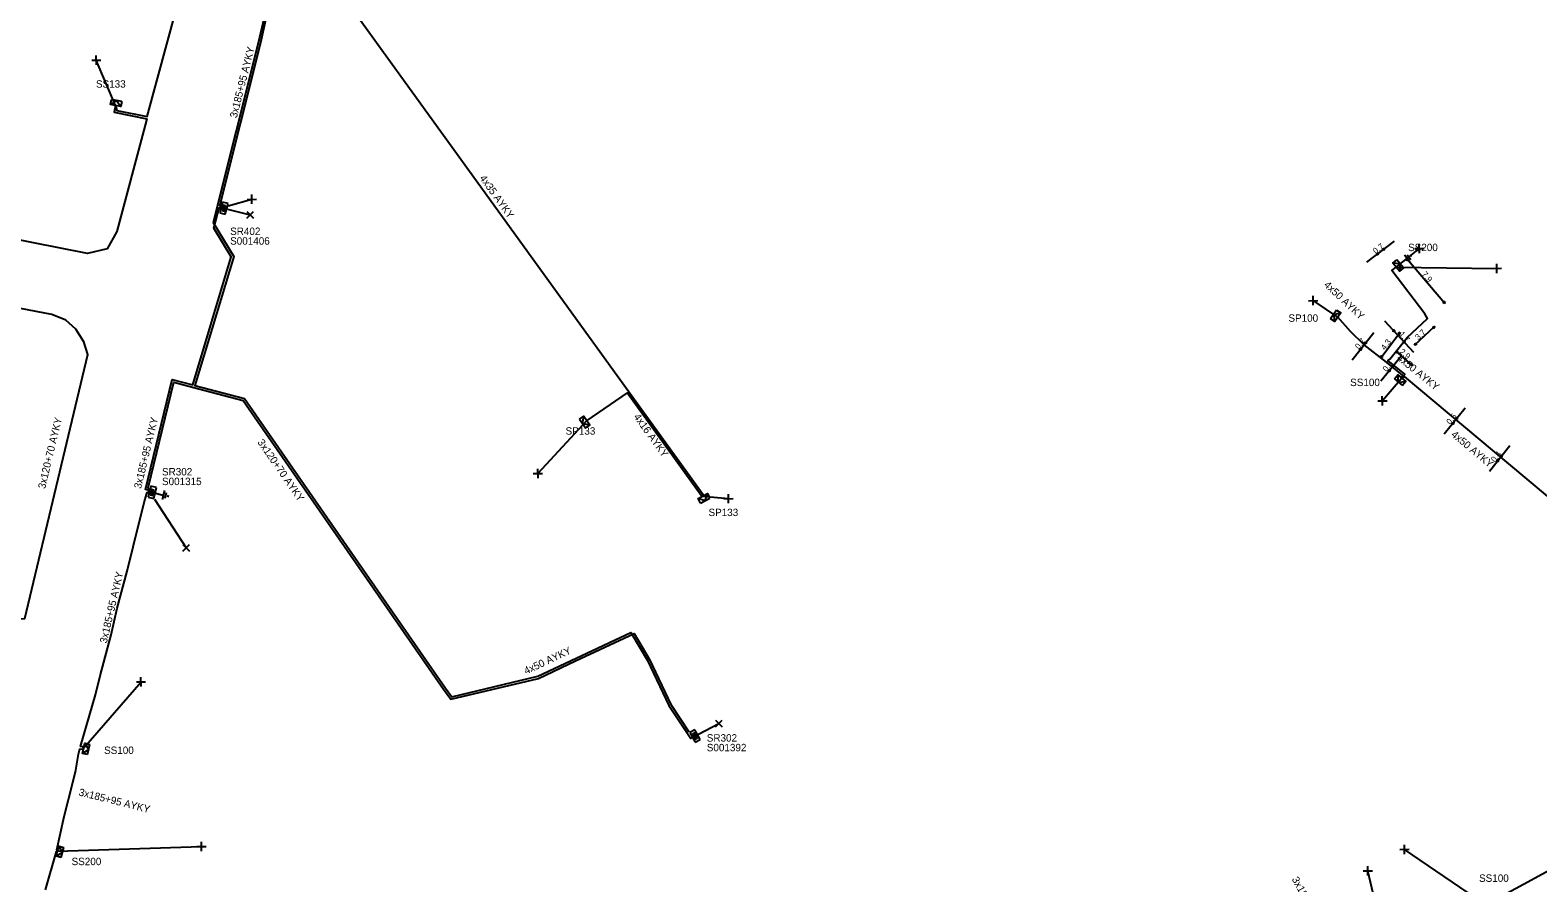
# Model space of a CAD drawing. Extents: x -762500 to -761285, y -1155006 to -1154135.
# Drawn here: x -761930.7 to -761728.2, y -1154659.6 to -1154545.1 of the extents above; entities that cross this region are included whole.
import ezdxf

# ---------------------------------------------------------------- set-up
doc = ezdxf.new("R2010")
doc.units = 0
for name, color, linetype in [('Vrstva 15', 7, 'Continuous'), ('Vrstva 28', 7, 'Continuous'), ('Vrstva 29', 7, 'Continuous'), ('Vrstva 30', 7, 'Continuous'), ('Vrstva 31', 7, 'Continuous'), ('Vrstva 33', 7, 'Continuous'), ('Vrstva 34', 7, 'Continuous'), ('Vrstva 40', 7, 'Continuous'), ('Vrstva 5', 7, 'Continuous'), ('Vrstva 59', 7, 'Continuous'), ('Vrstva 6', 7, 'Continuous')]:
    doc.layers.add(name, color=color, linetype=linetype)

msp = doc.modelspace()

# ---------------------------------------------------------------- linework, layer by layer
at = {"layer": 'Vrstva 15'}
for points in [[(-761746.748, -1154576.522), (-761745.763, -1154575.753)], [(-761746.148, -1154575.26), (-761745.379, -1154576.245)], [(-761745.755, -1154575.259), (-761745.271, -1154575.88)], [(-761745.353, -1154575.263), (-761745.271, -1154575.368)], [(-761745.271, -1154575.368), (-761745.192, -1154575.469)], [(-761914.028, -1154607.241), (-761912.815, -1154607.543)], [(-761912.664, -1154606.937), (-761912.966, -1154608.149)], [(-761912.421, -1154607.246), (-761912.612, -1154608.01)], [(-761912.208, -1154607.694), (-761912.239, -1154607.818)], [(-761912.176, -1154607.565), (-761912.208, -1154607.694)]]:
    msp.add_lwpolyline(points, dxfattribs=at)
at = {"layer": 'Vrstva 28'}
for points in [[(-761904.852, -1154568.18), (-761905.214, -1154569.635)], [(-761904.124, -1154568.361), (-761904.852, -1154568.18)], [(-761904.487, -1154569.817), (-761904.124, -1154568.361)], [(-761905.214, -1154569.635), (-761904.487, -1154569.817)], [(-761904.767, -1154568.596), (-761904.947, -1154569.318)], [(-761904.947, -1154569.318), (-761904.58, -1154569.41)], [(-761904.732, -1154568.654), (-761904.89, -1154569.284)], [(-761904.89, -1154569.284), (-761904.614, -1154569.353)], [(-761904.698, -1154568.711), (-761904.832, -1154569.25)], [(-761904.832, -1154569.25), (-761904.649, -1154569.295)], [(-761904.664, -1154568.768), (-761904.775, -1154569.215)], [(-761904.775, -1154569.215), (-761904.683, -1154569.238)], [(-761904.4, -1154568.688), (-761904.767, -1154568.596)], [(-761904.457, -1154568.722), (-761904.732, -1154568.654)], [(-761904.719, -1154569.186), (-761904.628, -1154568.82)], [(-761904.515, -1154568.757), (-761904.698, -1154568.711)], [(-761904.683, -1154569.238), (-761904.572, -1154568.791)], [(-761904.572, -1154568.791), (-761904.664, -1154568.768)], [(-761904.649, -1154569.295), (-761904.515, -1154568.757)], [(-761904.614, -1154569.353), (-761904.457, -1154568.722)], [(-761904.58, -1154569.41), (-761904.4, -1154568.688)], [(-761914.472, -1154606.359), (-761914.835, -1154607.814)], [(-761914.387, -1154606.776), (-761914.567, -1154607.498)], [(-761914.353, -1154606.833), (-761914.51, -1154607.463)], [(-761913.744, -1154606.54), (-761914.472, -1154606.359)], [(-761914.318, -1154606.89), (-761914.452, -1154607.429)], [(-761914.02, -1154606.867), (-761914.387, -1154606.776)], [(-761914.078, -1154606.902), (-761914.353, -1154606.833)], [(-761914.135, -1154606.936), (-761914.318, -1154606.89)], [(-761914.235, -1154607.532), (-761914.078, -1154606.902)], [(-761914.2, -1154607.589), (-761914.02, -1154606.867)], [(-761914.107, -1154607.996), (-761913.744, -1154606.54)], [(-761914.835, -1154607.814), (-761914.107, -1154607.996)], [(-761914.567, -1154607.498), (-761914.2, -1154607.589)], [(-761914.51, -1154607.463), (-761914.235, -1154607.532)], [(-761914.452, -1154607.429), (-761914.269, -1154607.475)], [(-761914.284, -1154606.947), (-761914.395, -1154607.394)], [(-761914.395, -1154607.394), (-761914.303, -1154607.417)], [(-761914.339, -1154607.366), (-761914.248, -1154606.999)], [(-761914.303, -1154607.417), (-761914.192, -1154606.97)], [(-761914.192, -1154606.97), (-761914.284, -1154606.947)], [(-761914.269, -1154607.475), (-761914.135, -1154606.936)], [(-761841.424, -1154639.065), (-761842.086, -1154639.417)], [(-761840.719, -1154640.389), (-761841.424, -1154639.065)], [(-761842.086, -1154639.417), (-761841.382, -1154640.742)], [(-761841.41, -1154639.493), (-761841.744, -1154639.67)], [(-761841.744, -1154639.67), (-761841.395, -1154640.327)], [(-761841.43, -1154639.557), (-761841.68, -1154639.69)], [(-761841.68, -1154639.69), (-761841.375, -1154640.263)], [(-761841.449, -1154639.62), (-761841.616, -1154639.709)], [(-761841.616, -1154639.709), (-761841.355, -1154640.199)], [(-761841.469, -1154639.684), (-761841.552, -1154639.729)], [(-761841.552, -1154639.729), (-761841.336, -1154640.135)], [(-761841.314, -1154640.077), (-761841.491, -1154639.743)], [(-761841.253, -1154640.091), (-761841.469, -1154639.684)], [(-761841.189, -1154640.111), (-761841.449, -1154639.62)], [(-761841.125, -1154640.13), (-761841.43, -1154639.557)], [(-761841.061, -1154640.15), (-761841.41, -1154639.493)], [(-761841.395, -1154640.327), (-761841.061, -1154640.15)], [(-761841.382, -1154640.742), (-761840.719, -1154640.389)], [(-761841.375, -1154640.263), (-761841.125, -1154640.13)], [(-761841.355, -1154640.199), (-761841.189, -1154640.111)], [(-761841.336, -1154640.135), (-761841.253, -1154640.091)]]:
    msp.add_lwpolyline(points, dxfattribs=at)
at = {"layer": 'Vrstva 31'}
for points in [[(-761918.406, -1154554.656), (-761918.54, -1154555.343), (-761919.914, -1154555.076), (-761919.781, -1154554.389)], [(-761919.094, -1154554.523), (-761919.914, -1154555.076)], [(-761918.406, -1154554.656), (-761919.781, -1154554.389)], [(-761919.094, -1154554.523), (-761918.54, -1154555.343)], [(-761746.264, -1154577.025), (-761746.808, -1154577.466), (-761747.689, -1154576.378), (-761747.145, -1154575.937)], [(-761746.704, -1154576.481), (-761747.689, -1154576.378)], [(-761746.264, -1154577.025), (-761747.145, -1154575.937)], [(-761746.704, -1154576.481), (-761746.808, -1154577.466)], [(-761755.267, -1154582.685), (-761756.05, -1154583.846)], [(-761755.267, -1154582.685), (-761754.687, -1154583.077), (-761755.47, -1154584.237), (-761756.05, -1154583.846)], [(-761755.659, -1154583.266), (-761754.687, -1154583.077)], [(-761755.659, -1154583.266), (-761755.47, -1154584.237)], [(-761747.489, -1154591.924), (-761747.039, -1154591.388), (-761745.967, -1154592.288), (-761746.417, -1154592.824)], [(-761747.489, -1154591.924), (-761746.417, -1154592.824)], [(-761746.953, -1154592.374), (-761747.039, -1154591.388)], [(-761746.953, -1154592.374), (-761745.967, -1154592.288)], [(-761856.919, -1154597.363), (-761856.353, -1154596.952), (-761855.53, -1154598.085), (-761856.097, -1154598.496)], [(-761856.919, -1154597.363), (-761856.097, -1154598.496)], [(-761856.508, -1154597.93), (-761856.353, -1154596.952)], [(-761856.508, -1154597.93), (-761855.53, -1154598.085)], [(-761840.652, -1154608.618), (-761840.981, -1154608), (-761839.744, -1154607.343), (-761839.416, -1154607.961)], [(-761840.034, -1154608.29), (-761840.981, -1154608)], [(-761840.652, -1154608.618), (-761839.416, -1154607.961)], [(-761840.034, -1154608.29), (-761839.744, -1154607.343)], [(-761923.001, -1154642.402), (-761923.68, -1154642.233), (-761923.341, -1154640.874), (-761922.662, -1154641.044)], [(-761922.831, -1154641.723), (-761923.341, -1154640.874)], [(-761923.001, -1154642.402), (-761922.662, -1154641.044)], [(-761922.831, -1154641.723), (-761923.68, -1154642.233)], [(-761926.51, -1154656.221), (-761927.189, -1154656.052), (-761926.851, -1154654.693), (-761926.172, -1154654.863)], [(-761926.341, -1154655.542), (-761926.851, -1154654.693)], [(-761926.51, -1154656.221), (-761926.172, -1154654.863)], [(-761926.341, -1154655.542), (-761927.189, -1154656.052)]]:
    msp.add_lwpolyline(points, dxfattribs=at)
at = {"layer": 'Vrstva 34'}
for points in [[(-761922.435, -1154549.141), (-761921.185, -1154549.119)], [(-761921.799, -1154549.755), (-761921.821, -1154548.505)], [(-761901.545, -1154567.821), (-761900.295, -1154567.799)], [(-761900.909, -1154568.435), (-761900.931, -1154567.185)], [(-761901.592, -1154569.438), (-761900.708, -1154570.322)], [(-761901.592, -1154570.322), (-761900.708, -1154569.438)], [(-761744.755, -1154574.431), (-761743.505, -1154574.409)], [(-761744.119, -1154575.045), (-761744.141, -1154573.795)], [(-761733.729, -1154577.715), (-761733.751, -1154576.465)], [(-761734.365, -1154577.101), (-761733.115, -1154577.079)], [(-761759.025, -1154581.431), (-761757.775, -1154581.409)], [(-761758.389, -1154582.045), (-761758.411, -1154580.795)], [(-761749.089, -1154595.505), (-761749.111, -1154594.255)], [(-761749.725, -1154594.891), (-761748.475, -1154594.869)], [(-761863.125, -1154604.641), (-761861.875, -1154604.619)], [(-761862.489, -1154605.255), (-761862.511, -1154604.005)], [(-761837.535, -1154608.031), (-761836.285, -1154608.009)], [(-761836.899, -1154608.645), (-761836.921, -1154607.395)], [(-761910.192, -1154614.188), (-761909.308, -1154615.072)], [(-761910.192, -1154615.072), (-761909.308, -1154614.188)], [(-761916.435, -1154632.641), (-761915.185, -1154632.619)], [(-761915.799, -1154633.255), (-761915.821, -1154632.005)], [(-761838.642, -1154637.768), (-761837.758, -1154638.652)], [(-761838.642, -1154638.652), (-761837.758, -1154637.768)], [(-761908.315, -1154654.761), (-761907.065, -1154654.739)], [(-761907.679, -1154655.375), (-761907.701, -1154654.125)], [(-761746.755, -1154655.141), (-761745.505, -1154655.119)], [(-761746.119, -1154655.755), (-761746.141, -1154654.505)], [(-761751.049, -1154658.625), (-761751.071, -1154657.375)], [(-761751.685, -1154658.011), (-761750.435, -1154657.989)]]:
    msp.add_lwpolyline(points, dxfattribs=at)
at = {"layer": 'Vrstva 40'}
for points in [[(-761751.21, -1154576.24), (-761747.49, -1154573.44)], [(-761740.7, -1154581.81), (-761745.85, -1154575.78)], [(-761748.82, -1154584.15), (-761744.92, -1154588.32)], [(-761753.18, -1154589.35), (-761750.23, -1154585.72)], [(-761749.33, -1154589.11), (-761746.72, -1154585.65)], [(-761744.78, -1154587.41), (-761742.08, -1154584.87)], [(-761745.07, -1154590.14), (-761747.26, -1154588.21)], [(-761749.33, -1154592.21), (-761746.51, -1154588.74)], [(-761740.79, -1154599.3), (-761737.97, -1154595.83)], [(-761734.74, -1154604.34), (-761732, -1154600.87)]]:
    msp.add_lwpolyline(points, dxfattribs=at)
for points in [[(-761749.092, -1154574.651), (-761748.957, -1154574.418), (-761748.831, -1154574.585)], [(-761749.608, -1154575.039), (-761749.744, -1154575.272), (-761749.869, -1154575.105)], [(-761745.851, -1154575.778), (-761745.609, -1154575.897), (-761745.767, -1154576.035)], [(-761740.698, -1154581.812), (-761740.94, -1154581.692), (-761740.783, -1154581.555)], [(-761747.449, -1154585.612), (-761747.697, -1154585.506), (-761747.546, -1154585.36)], [(-761746.718, -1154585.648), (-761746.784, -1154585.909), (-761746.951, -1154585.784)], [(-761742.079, -1154584.869), (-761742.185, -1154585.117), (-761742.33, -1154584.966)], [(-761751.918, -1154587.798), (-761751.993, -1154588.057), (-761752.156, -1154587.926)], [(-761751.492, -1154587.272), (-761751.417, -1154587.013), (-761751.254, -1154587.144)], [(-761747.262, -1154588.208), (-761747.006, -1154588.292), (-761747.143, -1154588.45)], [(-761746.282, -1154586.858), (-761746.034, -1154586.964), (-761746.184, -1154587.109)], [(-761744.781, -1154587.412), (-761744.675, -1154587.164), (-761744.53, -1154587.314)], [(-761749.331, -1154589.112), (-761749.265, -1154588.85), (-761749.098, -1154588.976)], [(-761748.068, -1154590.658), (-761748.143, -1154590.917), (-761748.306, -1154590.786)], [(-761747.772, -1154590.292), (-761747.697, -1154590.033), (-761747.534, -1154590.164)], [(-761745.068, -1154590.142), (-761745.325, -1154590.058), (-761745.187, -1154589.9)], [(-761739.528, -1154597.748), (-761739.603, -1154598.007), (-761739.766, -1154597.876)], [(-761739.232, -1154597.382), (-761739.157, -1154597.123), (-761738.994, -1154597.254)], [(-761733.498, -1154602.768), (-761733.569, -1154603.028), (-761733.734, -1154602.9)], [(-761733.242, -1154602.442), (-761733.171, -1154602.182), (-761733.006, -1154602.31)]]:
    msp.add_lwpolyline(points, close=True, dxfattribs=at)
at = {"layer": 'Vrstva 5'}
for points in [[(-761895.61, -1154531.16), (-761896.11, -1154531.47), (-761897.05, -1154535.37), (-761899.2, -1154543), (-761900.01, -1154546.67), (-761906.12, -1154570.94), (-761903.36, -1154575.51), (-761908.56, -1154592.81), (-761901.89, -1154594.56), (-761874.94, -1154633.46), (-761874.08, -1154634.63), (-761862.51, -1154631.88), (-761850.03, -1154626), (-761847.78, -1154629.75), (-761844.92, -1154635.82), (-761841.98, -1154640.25), (-761841.84, -1154640.14)], [(-761905.14, -1154568.82), (-761905.24, -1154568.67), (-761899.72, -1154546.74), (-761898.91, -1154543.07), (-761896.76, -1154535.45), (-761895.85, -1154531.66), (-761895.64, -1154531.29)], [(-761894.78, -1154532), (-761840.33, -1154607.44), (-761840.36, -1154607.67)], [(-761919.23, -1154555.21), (-761919.07, -1154555.86), (-761914.99, -1154556.7), (-761908.46, -1154532.58), (-761908.81, -1154532.18)], [(-761919.23, -1154555.21), (-761919.42, -1154556.09), (-761915.01, -1154557), (-761915.24, -1154557.84), (-761919.07, -1154572.15), (-761920.34, -1154574.46), (-761922.98, -1154575.07), (-761945.03, -1154570.76)], [(-761914.78, -1154607.06), (-761914.9, -1154606.86), (-761915.19, -1154606.8), (-761911.63, -1154592.03), (-761908.85, -1154592.74), (-761903.69, -1154575.55), (-761906.01, -1154571.7), (-761905.32, -1154568.94), (-761905.17, -1154568.94)], [(-761931.99, -1154624.17), (-761931.42, -1154624.12), (-761922.94, -1154588.66), (-761923.49, -1154586.95), (-761924.58, -1154585.24), (-761925.92, -1154584.04), (-761927.8, -1154583.28), (-761975.02, -1154574.25), (-761975.44, -1154574.61)], [(-761746.5, -1154591.84), (-761746.07, -1154591.31), (-761748.35, -1154589.48), (-761748.09, -1154589.26), (-761745.76, -1154586.37), (-761743.06, -1154583.83), (-761743.42, -1154583.18), (-761747.85, -1154577.38), (-761747.25, -1154576.92)], [(-761746.5, -1154591.84), (-761746.4, -1154591.43), (-761748.57, -1154589.68), (-761751.53, -1154587.34), (-761753.4, -1154585.58), (-761755.08, -1154583.66)], [(-761914.74, -1154606.93), (-761914.83, -1154606.56), (-761911.41, -1154592.39), (-761908.91, -1154593.03), (-761902.07, -1154594.82), (-761875.18, -1154633.63), (-761874.2, -1154634.97), (-761862.41, -1154632.16), (-761857.47, -1154629.8), (-761849.6, -1154626.13), (-761847.51, -1154629.61), (-761844.66, -1154635.67), (-761842.22, -1154639.34)], [(-761702.95, -1154635.12), (-761702.82, -1154634.74), (-761710.5, -1154625.1), (-761713.94, -1154620.4), (-761715.4, -1154618.6), (-761711.39, -1154615.39), (-761711.64, -1154614.55), (-761711.5, -1154614.39), (-761711.5, -1154614.15), (-761711.72, -1154614.19), (-761711.97, -1154614.49), (-761711.72, -1154615.27), (-761715.58, -1154618.36), (-761717.15, -1154616.55), (-761718.98, -1154614.85), (-761720.21, -1154613.42), (-761720.66, -1154613.62), (-761720.42, -1154613.21), (-761722.83, -1154611.14), (-761734.06, -1154601.73), (-761746.14, -1154591.63), (-761746.5, -1154591.84)], [(-761840.36, -1154607.67), (-761840.59, -1154607.61), (-761850.52, -1154593.81), (-761855.94, -1154597.52)], [(-761928.65, -1154660.56), (-761927.17, -1154655.43), (-761927.02, -1154655.37), (-761927.1, -1154655.18), (-761926.11, -1154650.7), (-761925.02, -1154646.33), (-761924.56, -1154644.5), (-761924.21, -1154642.32), (-761924.02, -1154641.61), (-761923.68, -1154641.66), (-761923.51, -1154641.55), (-761923.61, -1154641.37), (-761923.93, -1154641.31), (-761921.94, -1154634.37), (-761921.31, -1154631.84), (-761919.83, -1154626.33), (-761918.99, -1154622.72), (-761917.68, -1154617.75), (-761916.07, -1154611.24), (-761915.26, -1154608.03), (-761915, -1154607.19), (-761914.81, -1154607.19)], [(-761702.95, -1154635.12), (-761702.54, -1154635.17), (-761702.16, -1154635.93), (-761701.48, -1154638.13), (-761701.49, -1154641.07), (-761702.39, -1154643.28), (-761703.91, -1154644.9), (-761707.18, -1154646.86), (-761716.24, -1154652.23), (-761729.56, -1154659.53), (-761735.14, -1154662.55), (-761735.5, -1154662.4), (-761735.51, -1154662.76), (-761748.08, -1154669.62), (-761748.37, -1154669.45)]]:
    msp.add_lwpolyline(points, dxfattribs=at)
at = {"layer": 'Vrstva 59'}
for points in [[(-761919.23, -1154555.21), (-761921.81, -1154549.13)], [(-761904.11, -1154568.67), (-761900.92, -1154567.81)], [(-761904.18, -1154569.12), (-761901.15, -1154569.88)], [(-761747.25, -1154576.92), (-761744.13, -1154574.42)], [(-761747.25, -1154576.92), (-761733.74, -1154577.09)], [(-761755.08, -1154583.66), (-761758.4, -1154581.42)], [(-761746.5, -1154591.84), (-761749.1, -1154594.88)], [(-761855.94, -1154597.52), (-761862.5, -1154604.63)], [(-761913.99, -1154608.1), (-761909.75, -1154614.63)], [(-761840.36, -1154607.67), (-761836.91, -1154608.02)], [(-761923.51, -1154641.55), (-761915.81, -1154632.63)], [(-761840.95, -1154639.67), (-761838.2, -1154638.21)], [(-761927.02, -1154655.37), (-761907.69, -1154654.75)], [(-761735.5, -1154662.4), (-761746.13, -1154655.13)], [(-761748.37, -1154669.45), (-761751.06, -1154658)]]:
    msp.add_lwpolyline(points, dxfattribs=at)

# ---------------------------------------------------------------- texts
at = {"layer": 'Vrstva 29'}
for s, p in [('S001406', (-761903.84, -1154573.9)), ('S001315', (-761912.99, -1154606.2)), ('S001392', (-761839.83, -1154641.95))]:
    msp.add_text(s, height=0.9943, dxfattribs=at).set_placement(p)
at = {"layer": 'Vrstva 30'}
for s, p in [('SR402', (-761903.84, -1154572.6)), ('SR302', (-761912.99, -1154604.9)), ('SR302', (-761839.83, -1154640.65))]:
    msp.add_text(s, height=0.9943, dxfattribs=at).set_placement(p)
at = {"layer": 'Vrstva 33'}
for s, p in [('SS133', (-761921.86, -1154552.81)), ('SS200', (-761745.65, -1154574.77)), ('SP100', (-761761.72, -1154584.26)), ('SS100', (-761753.43, -1154592.9)), ('SP133', (-761858.79, -1154599.42)), ('SP133', (-761839.6, -1154610.36)), ('SS100', (-761920.77, -1154642.31)), ('SS200', (-761925.13, -1154657.25)), ('SS100', (-761736.12, -1154659.49))]:
    msp.add_text(s, height=0.9943, dxfattribs=at).set_placement(p)
at = {"layer": 'Vrstva 40'}
for s, rotation, p in [('0,7', 36.98028, (-761750, -1154575.19)), ('7,9', 310.49924, (-761743.87, -1154577.91)), ('0,7', 50.9463, (-761752.25, -1154588.02)), ('4,3', 52.96197, (-761748.76, -1154588.15)), ('1,7', 313.1076, (-761746.92, -1154586)), ('3,7', 43.25109, (-761744.28, -1154586.78)), ('2,9', 318.6691, (-761746.88, -1154588.39)), ('0,5', 50.97259, (-761748.53, -1154591.04)), ('0,5', 50.9668, (-761739.99, -1154598.13)), ('0,4', 51.76196, (-761733.99, -1154603.2))]:
    msp.add_text(s, height=0.7954, rotation=rotation, dxfattribs=at).set_placement(p)
at = {"layer": 'Vrstva 6'}
for s, height, rotation, p in [('3x185+95 AYKY', 0.99428, 75.86914, (-761902.95, -1154556.96)), ('4x35 AYKY', 0.9943, 305.81417, (-761870.41, -1154564.97)), ('4x50 AYKY', 0.9943, 316.73571, (-761757.03, -1154579.41)), ('4x50 AYKY', 0.9943, 321.12326, (-761747.25, -1154589.28)), ('3x120+70 AYKY', 0.99429, 76.56397, (-761928.69, -1154606.76)), ('3x185+95 AYKY', 0.99429, 76.43779, (-761915.81, -1154606.75)), ('4x16 AYKY', 0.9943, 305.75389, (-761849.71, -1154597.04)), ('3x120+70 AYKY', 0.99429, 304.71664, (-761900.22, -1154600.45)), ('4x50 AYKY', 0.9943, 320.03921, (-761739.95, -1154599.56)), ('3x185+95 AYKY', 0.99428, 76.9011, (-761920.41, -1154627.51)), ('4x50 AYKY', 0.9943, 25.21284, (-761864.09, -1154631.66)), ('3x185+95 AYKY', 0.99428, 345.99461, (-761924.24, -1154647.88)), ('3x185+95 AYKY', 0.99429, 298.71428, (-761761.3, -1154659.13))]:
    msp.add_text(s, height=height, rotation=rotation, dxfattribs=at).set_placement(p)

doc.saveas('drawing.dxf')
